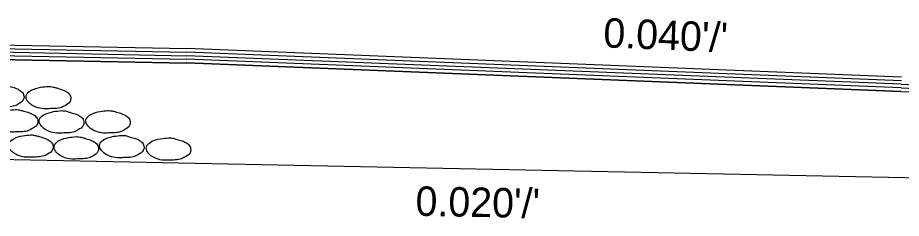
# Model space of a CAD drawing. Extents: x 1931522 to 1935523, y 600380 to 605075.
# Drawn here: x 1933166.4 to 1933348.9, y 604769.5 to 604810.9 of the extents above; entities that cross this region are included whole.
import ezdxf

# ---------------------------------------------------------------- set-up
doc = ezdxf.new("R2010")
doc.units = 0
doc.layers.add('Default', color=7, linetype='Continuous')

msp = doc.modelspace()

# ---------------------------------------------------------------- linework, layer by layer
at = {"layer": 'Default'}
for p, q in [((1933148.16, 604805.58), (1933201.33, 604804.52)), ((1933148.16, 604804.84), (1933201.33, 604803.78)), ((1933148.19, 604804.1), (1933201.33, 604803.04)), ((1933348.95, 604798.61), (1933201.33, 604804.52)), ((1933348.95, 604797.88), (1933201.33, 604803.78)), ((1933148.21, 604803.36), (1933201.33, 604802.3)), ((1933148.23, 604802.62), (1933201.28, 604801.57)), ((1933148.23, 604802.53), (1933201.33, 604801.47)), ((1933348.9, 604797.14), (1933201.28, 604803.04)), ((1933348.9, 604796.4), (1933201.28, 604802.3)), ((1933348.85, 604795.66), (1933201.23, 604801.57)), ((1933348.85, 604795.56), (1933201.33, 604801.47)), ((1933348.89, 604797.14), (1933483.54, 604791.75)), ((1933348.83, 604795.66), (1933483.48, 604790.27)), ((1933348.85, 604796.4), (1933483.51, 604791.01)), ((1933147.68, 604781.96), (1933541.06, 604774.13))]:
    msp.add_line(p, q, dxfattribs=at)
for points in [[(1933163.07, 604797.04), (1933161.45, 604796.84), (1933159.58, 604796.25), (1933158.59, 604795.42), (1933158.44, 604794.83), (1933158.89, 604793.84), (1933159.43, 604793.35), (1933160.51, 604792.76), (1933162.09, 604792.41), (1933162.92, 604792.41), (1933164.15, 604792.46), (1933165.48, 604792.61), (1933166.51, 604793.05), (1933167.55, 604793.94), (1933167.7, 604794.53), (1933167.4, 604795.42), (1933166.66, 604796.01), (1933165.92, 604796.35), (1933164.79, 604796.7), (1933164.1, 604796.89), (1933163.07, 604797.04)], [(1933172.73, 604796.72), (1933171.11, 604796.52), (1933169.24, 604795.93), (1933168.25, 604795.1), (1933168.11, 604794.51), (1933168.55, 604793.52), (1933169.09, 604793.03), (1933170.17, 604792.44), (1933171.75, 604792.09), (1933172.58, 604792.09), (1933173.81, 604792.14), (1933175.14, 604792.29), (1933176.18, 604792.73), (1933177.21, 604793.62), (1933177.36, 604794.21), (1933177.06, 604795.1), (1933176.32, 604795.69), (1933175.59, 604796.03), (1933174.45, 604796.38), (1933173.76, 604796.57), (1933172.73, 604796.72)], [(1933165.93, 604791.92), (1933164.31, 604791.73), (1933162.44, 604791.13), (1933161.45, 604790.3), (1933161.31, 604789.76), (1933161.75, 604788.77), (1933162.29, 604788.23), (1933163.37, 604787.64), (1933164.95, 604787.3), (1933165.78, 604787.3), (1933167.02, 604787.35), (1933168.34, 604787.49), (1933169.38, 604787.99), (1933170.41, 604788.82), (1933170.56, 604789.46), (1933170.26, 604790.35), (1933169.52, 604790.94), (1933168.79, 604791.28), (1933167.65, 604791.58), (1933166.97, 604791.82), (1933165.93, 604791.92)], [(1933175.45, 604791.7), (1933173.82, 604791.5), (1933171.95, 604790.91), (1933170.97, 604790.08), (1933170.82, 604789.54), (1933171.26, 604788.55), (1933171.8, 604788.01), (1933172.89, 604787.42), (1933174.46, 604787.08), (1933175.3, 604787.08), (1933176.53, 604787.12), (1933177.86, 604787.27), (1933178.89, 604787.76), (1933179.92, 604788.6), (1933180.07, 604789.24), (1933179.78, 604790.13), (1933179.04, 604790.72), (1933178.3, 604791.06), (1933177.17, 604791.36), (1933176.48, 604791.6), (1933175.45, 604791.7)], [(1933185.03, 604791.72), (1933183.4, 604791.52), (1933181.53, 604790.93), (1933180.6, 604790.09), (1933180.45, 604789.55), (1933180.89, 604788.57), (1933181.43, 604788.03), (1933182.52, 604787.44), (1933184.09, 604787.09), (1933184.88, 604787.09), (1933186.11, 604787.14), (1933187.44, 604787.29), (1933188.52, 604787.78), (1933189.5, 604788.62), (1933189.65, 604789.26), (1933189.36, 604790.14), (1933188.62, 604790.73), (1933187.88, 604791.08), (1933186.8, 604791.37), (1933186.06, 604791.62), (1933185.03, 604791.72)], [(1933169.09, 604786.71), (1933167.47, 604786.51), (1933165.6, 604785.92), (1933164.66, 604785.08), (1933164.51, 604784.49), (1933164.96, 604783.51), (1933165.5, 604783.02), (1933166.58, 604782.43), (1933168.16, 604782.08), (1933168.94, 604782.08), (1933170.17, 604782.13), (1933171.5, 604782.28), (1933172.58, 604782.72), (1933173.57, 604783.61), (1933173.72, 604784.2), (1933173.42, 604785.08), (1933172.68, 604785.67), (1933171.94, 604786.02), (1933170.86, 604786.36), (1933170.12, 604786.56), (1933169.09, 604786.71)], [(1933178.49, 604786.35), (1933176.86, 604786.15), (1933174.99, 604785.56), (1933174.06, 604784.72), (1933173.91, 604784.13), (1933174.36, 604783.15), (1933174.9, 604782.65), (1933175.98, 604782.06), (1933177.55, 604781.72), (1933178.34, 604781.72), (1933179.57, 604781.77), (1933180.9, 604781.92), (1933181.98, 604782.36), (1933182.97, 604783.25), (1933183.11, 604783.84), (1933182.82, 604784.72), (1933182.08, 604785.31), (1933181.34, 604785.66), (1933180.26, 604786), (1933179.52, 604786.2), (1933178.49, 604786.35)], [(1933187.86, 604786.61), (1933186.24, 604786.41), (1933184.37, 604785.82), (1933183.43, 604784.98), (1933183.29, 604784.44), (1933183.73, 604783.46), (1933184.27, 604782.92), (1933185.35, 604782.33), (1933186.93, 604781.98), (1933187.72, 604781.98), (1933188.95, 604782.03), (1933190.27, 604782.18), (1933191.36, 604782.67), (1933192.34, 604783.51), (1933192.49, 604784.15), (1933192.19, 604785.03), (1933191.45, 604785.62), (1933190.72, 604785.97), (1933189.63, 604786.26), (1933188.9, 604786.51), (1933187.86, 604786.61)], [(1933197.51, 604786.1), (1933195.88, 604785.9), (1933194.01, 604785.31), (1933193.08, 604784.48), (1933192.93, 604783.93), (1933193.37, 604782.95), (1933193.92, 604782.41), (1933195, 604781.82), (1933196.57, 604781.47), (1933197.36, 604781.47), (1933198.59, 604781.52), (1933199.92, 604781.67), (1933201, 604782.16), (1933201.99, 604783), (1933202.13, 604783.64), (1933201.84, 604784.52), (1933201.1, 604785.12), (1933200.36, 604785.46), (1933199.28, 604785.75), (1933198.54, 604786), (1933197.51, 604786.1)]]:
    msp.add_spline(points, degree=3, dxfattribs=at)

# ---------------------------------------------------------------- texts
for s, rotation, p in [("0.040'/'", 357.7094, (1933287.27, 604804.77)), ("0.020'/'", 358.8537, (1933248.52, 604770.03))]:
    msp.add_text(s, height=6.075, rotation=rotation, dxfattribs=at).set_placement(p)

doc.saveas('drawing.dxf')
